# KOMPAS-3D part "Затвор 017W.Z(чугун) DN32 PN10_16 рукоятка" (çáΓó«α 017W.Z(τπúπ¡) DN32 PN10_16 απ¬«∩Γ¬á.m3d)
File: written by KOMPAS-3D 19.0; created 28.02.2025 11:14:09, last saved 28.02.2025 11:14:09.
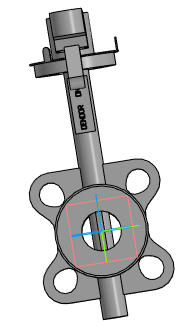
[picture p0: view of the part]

Document properties: Автор: Евгений; Полное имя файла: Затвор 017W.Z(чугун) DN32 PN10_16 рукоятка.a3d

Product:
- Part/product: Затвор 017W.Z(чугун) DN32 PN10_16 рукоятка
    Масса: 3.05707

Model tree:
1. Операция без истории:1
